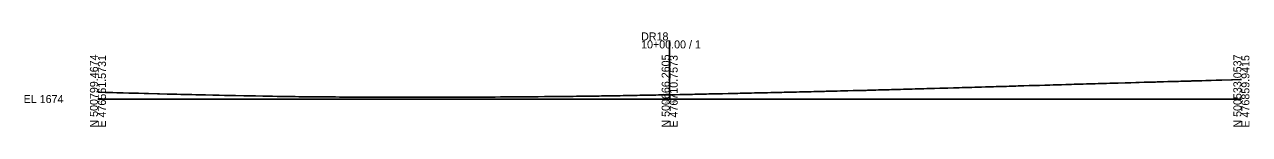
# Model space of a CAD drawing. Extents: x -26 to 403, y -10 to 2113.
# Drawn here: x -25.7 to 402.8, y -9.7 to 23.4 of the extents above; entities that cross this region are included whole.
import ezdxf

# ---------------------------------------------------------------- set-up
doc = ezdxf.new("R2010")
doc.units = 0
for name, color, linetype in [('Exist Cross Section Cell', 7, 'Continuous'), ('Exist XS Center Line Elevation Label', 7, 'Continuous'), ('Exist XS Ground Line', 7, 'Continuous')]:
    doc.layers.add(name, color=color, linetype=linetype)

msp = doc.modelspace()

# ---------------------------------------------------------------- linework, layer by layer
at = {"layer": 'Exist Cross Section Cell'}
for p, q in [((200, 0), (200, 20.54)), ((0, 0), (200, 0)), ((200, 0), (400, 0))]:
    msp.add_line(p, q, dxfattribs=at)
at = {"layer": 'Exist XS Ground Line'}
msp.add_lwpolyline([(0, 2.42), (0.73, 2.4), (2.59, 2.34), (4.05, 2.3), (5.22, 2.26), (6.63, 2.22), (7.05, 2.21), (7.43, 2.2), (8.77, 2.16), (10.78, 2.1), (12.25, 2.06), (14.13, 2.02), (16.16, 1.96), (17.67, 1.92), (20.83, 1.84), (21.17, 1.83), (21.56, 1.82), (24.18, 1.75), (25.12, 1.73), (26.37, 1.7), (27.54, 1.67), (28.97, 1.64), (30.88, 1.59), (32.83, 1.54), (34.24, 1.51), (36.37, 1.47), (37.58, 1.44), (40.19, 1.38), (40.93, 1.36), (42.39, 1.33), (44.29, 1.28), (47.65, 1.21), (48.11, 1.2), (51, 1.14), (51.3, 1.14), (51.64, 1.13), (54.34, 1.08), (55.14, 1.07), (57.69, 1.02), (58.27, 1.01), (59.05, 0.99), (60.15, 0.97), (61.05, 0.96), (62.73, 0.93), (63.58, 0.91), (64.43, 0.9), (65.36, 0.89), (66.45, 0.88), (67.75, 0.86), (68.99, 0.84), (70.3, 0.83), (71.1, 0.82), (73.83, 0.79), (74.48, 0.78), (76.05, 0.77), (77.85, 0.75), (81.34, 0.73), (83.15, 0.72), (84.51, 0.71), (84.88, 0.71), (85.4, 0.7), (88.11, 0.69), (88.87, 0.68), (90.1, 0.68), (91.2, 0.68), (92.06, 0.68), (92.92, 0.68), (94.55, 0.67), (95.18, 0.67), (96.38, 0.66), (97.18, 0.66), (97.91, 0.66), (99.53, 0.66), (100.41, 0.66), (101.26, 0.66), (102.55, 0.65), (103.86, 0.65), (104.25, 0.66), (104.61, 0.65), (105.64, 0.65), (107.97, 0.65), (109.87, 0.64), (111.33, 0.65), (112.88, 0.64), (114.52, 0.65), (115.02, 0.65), (115.58, 0.65), (118.26, 0.65), (119, 0.65), (121.31, 0.66), (122.29, 0.66), (122.79, 0.66), (123.77, 0.66), (124.72, 0.66), (125.36, 0.67), (126.66, 0.67), (127.43, 0.67), (128.3, 0.67), (129.69, 0.67), (130.21, 0.67), (130.84, 0.67), (131.42, 0.67), (132.68, 0.68), (134.19, 0.69), (134.77, 0.69), (135.46, 0.69), (137.2, 0.7), (137.78, 0.7), (138.16, 0.7), (138.94, 0.71), (140.86, 0.72), (141.75, 0.73), (143.6, 0.74), (144.47, 0.74), (145.58, 0.75), (146.27, 0.75), (147.34, 0.76), (148.62, 0.77), (150.18, 0.78), (151.12, 0.79), (151.43, 0.79), (153.39, 0.81), (153.69, 0.81), (154.01, 0.81), (156.23, 0.84), (158.7, 0.86), (159.82, 0.87), (161.18, 0.88), (163.33, 0.9), (163.87, 0.91), (165.71, 0.93), (166.2, 0.93), (167.39, 0.95), (168.27, 0.96), (168.62, 0.96), (170.84, 1), (171.45, 1.01), (172.02, 1.02), (173.46, 1.04), (175.33, 1.06), (176.14, 1.08), (178.15, 1.11), (178.51, 1.12), (178.96, 1.12), (180.86, 1.15), (182.66, 1.18), (183.68, 1.2), (185.32, 1.23), (185.96, 1.24), (186.59, 1.25), (188.12, 1.28), (188.64, 1.29), (189.61, 1.3), (191.02, 1.33), (192.33, 1.35), (193.36, 1.37), (194.17, 1.38), (195.18, 1.4), (196.08, 1.42), (197.75, 1.45), (198.3, 1.46), (198.8, 1.47), (200, 1.49), (200.69, 1.5), (201.88, 1.53), (203.51, 1.56), (205.42, 1.6), (206.36, 1.62), (207.95, 1.64), (208.76, 1.66), (209.07, 1.67), (210.83, 1.71), (211.84, 1.73), (212.85, 1.75), (213.75, 1.77), (214.3, 1.78), (215.19, 1.8), (215.91, 1.81), (216.67, 1.83), (217.32, 1.84), (218.54, 1.87), (220.48, 1.91), (221.54, 1.94), (223.87, 1.99), (224.69, 2.01), (225.49, 2.03), (226.84, 2.06), (228.07, 2.09), (228.58, 2.1), (229.7, 2.13), (232.02, 2.18), (234.17, 2.23), (235.42, 2.26), (237.08, 2.29), (238.92, 2.34), (239.23, 2.34), (240.07, 2.36), (241.43, 2.39), (242.01, 2.4), (242.99, 2.43), (244.37, 2.46), (245.37, 2.48), (246.01, 2.5), (246.72, 2.51), (247.41, 2.53), (248.71, 2.56), (249.55, 2.58), (250.45, 2.6), (251.57, 2.63), (252.05, 2.64), (253.08, 2.67), (254.18, 2.69), (254.71, 2.71), (255.54, 2.72), (256.88, 2.76), (258, 2.78), (258.65, 2.8), (259.75, 2.83), (261.54, 2.87), (261.91, 2.88), (262.27, 2.89), (264.2, 2.94), (265.44, 2.97), (267.33, 3.02), (268.77, 3.05), (269.24, 3.07), (270.29, 3.09), (272.15, 3.14), (273.03, 3.17), (274.61, 3.21), (275.52, 3.23), (276.77, 3.27), (277.61, 3.29), (278.87, 3.33), (280.7, 3.38), (281.82, 3.41), (282.23, 3.42), (284.18, 3.48), (284.88, 3.5), (285.87, 3.53), (287.16, 3.57), (288.12, 3.59), (288.93, 3.62), (290, 3.65), (291.61, 3.69), (292.12, 3.71), (292.65, 3.72), (294.48, 3.78), (295.66, 3.81), (297.36, 3.86), (299.25, 3.91), (301.24, 3.96), (302.32, 3.99), (302.95, 4.01), (304.17, 4.04), (305.66, 4.09), (306.79, 4.12), (307.16, 4.13), (308.48, 4.17), (309.04, 4.18), (310.49, 4.22), (311.45, 4.25), (312.39, 4.28), (313.27, 4.31), (314.27, 4.34), (314.59, 4.35), (315.67, 4.38), (316.55, 4.41), (317.86, 4.45), (318.72, 4.47), (319.6, 4.5), (321.11, 4.54), (321.93, 4.57), (322.6, 4.59), (323.94, 4.63), (325.71, 4.69), (326.78, 4.72), (329.33, 4.79), (331.26, 4.85), (333.02, 4.91), (334.18, 4.94), (335.86, 4.99), (336.24, 5.01), (336.71, 5.02), (337.13, 5.03), (338.57, 5.08), (339.22, 5.09), (339.87, 5.11), (340.53, 5.13), (341.54, 5.16), (342.92, 5.2), (343.87, 5.23), (344.64, 5.25), (345.82, 5.28), (346.61, 5.3), (347.77, 5.34), (348.82, 5.37), (349.88, 5.4), (351.24, 5.44), (352.01, 5.46), (352.85, 5.49), (354.01, 5.52), (355.41, 5.56), (355.91, 5.57), (356.84, 5.6), (359.32, 5.67), (361.37, 5.73), (363.05, 5.78), (364.25, 5.82), (366.05, 5.86), (366.83, 5.88), (368.68, 5.94), (369.36, 5.96), (369.92, 5.97), (370.56, 5.99), (371.61, 6.02), (372.71, 6.05), (374.31, 6.1), (376.06, 6.15), (376.99, 6.17), (378.04, 6.2), (378.78, 6.21), (379.41, 6.24), (380.54, 6.27), (381.83, 6.31), (382.3, 6.31), (382.72, 6.33), (385.53, 6.42), (386.12, 6.43), (387.62, 6.47), (389.47, 6.54), (391.15, 6.58), (392.8, 6.64), (393.14, 6.65), (396.52, 6.74), (396.85, 6.75), (399.53, 6.83), (400, 6.85)], dxfattribs=at)

# ---------------------------------------------------------------- texts
at = {"layer": 'Exist Cross Section Cell'}
for s, p in [('DR18', (190, 20.54)), ('10+00.00 / 1', (190, 17.74)), ('EL 1674', (-26, -1.4))]:
    msp.add_text(s, height=2.8, dxfattribs=at).set_placement(p)
for s, p in [('N 500799.4674', (0, -10)), ('E 476561.5731', (2.8, -10)), ('N 500666.2605', (200, -10)), ('E 476710.7573', (202.8, -10)), ('N 500533.0537', (400, -10)), ('E 476859.9415', (402.8, -10))]:
    msp.add_text(s, height=2.8, rotation=90, dxfattribs=at).set_placement(p)
at = {"layer": 'Exist XS Center Line Elevation Label'}
msp.add_text('1675.49', height=0.75, dxfattribs=at).set_placement((198.29, -1.26))

doc.saveas('drawing.dxf')
